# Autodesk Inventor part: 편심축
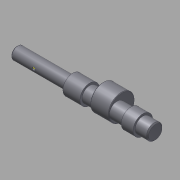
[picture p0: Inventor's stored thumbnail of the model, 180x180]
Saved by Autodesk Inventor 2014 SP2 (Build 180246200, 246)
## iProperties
Company: 한국ATC센터
Created: 2015-12
Part Number: 편심축
Document SubType Name: Modeling
Designer: mdu
Density: 7.86 g/cm^3
Mass: 225.292 g
Surface Area: 81.2402 cm^2
Volume: 28.6631 cm^3
Material: 강철, 연강
Appearance: 강철
Author: mdu
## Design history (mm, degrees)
sketch "스케치1"
  geometry: L1 (-86, 0)-(86, 0); L2 (-86, 0)-(-86, 6); L3 (-86, 6)-(-32, 6); L4 (-32, 6)-(-32, 9.5); L5 (-32, 9.5)-(-15.5, 9.5); L6 (-15.5, 9.5)-(-15.5, 7.5); L7 (-15.5, 7.5)-(48, 7.5); L8 (86, 6)-(86, 0); L9 (36, 7.5)-(36, 9.5); L10 (36, 9.5)-(24.5, 9.5); L11 (24.5, 9.5)-(24.5, 7.5); L12 (48, 7.5)-(48, 6); L13 (48, 6)-(86, 6); 2 further points
  constraints: 26 end point, 6 parallel, 6 perpendicular, 2 point on line, 1 coincident, 1 horizontal, 1 midpoint
  dimensions: "d1" = 12 diameter of L3 L1; "d2" = 15 diameter of L7 L1; "d4" = 16.5 distance of L4.end L5.end; "d5" = 19 diameter of L5 L1; "d24" = 11.5 distance of L9.end L10.end; "d25" = 19 diameter of L10 L1; "d27" = 40 distance between parallel lines of L11 L6; "d28" = 54 distance of L2.end L3.end; "d29" = 50 distance between parallel lines of L8 L9; "d41" = 38 distance between parallel lines of L8 L12; "d42" = 12 diameter of L13 L1
revolve "회전1" stored, may be unused: angle "d6" = 90 deg
node "작업 평면1"
sketch "스케치2"
  geometry: C1 r 7.5 at (0, 0) reference; C2 r 12.5 at (0, 4.5); 1 further point
  constraints: 1 centre point, 1 vertical alignment
  dimensions: "d8" = 4.5 distance of point (0, 0) C2.centre; "d9" = 25 diameter of C2
extrude "돌출1" join sketch "스케치2" distance "d10" = 18; taper "d11" = 0 deg
chamfer "모따기1" distance "d12" = 1; stored, may be unused: second distance "d13" = 2, angle "d14" = 45 deg
chamfer "모따기2" distance "d15" = 0.5; stored, may be unused: second distance "d16" = 2, angle "d17" = 45 deg
node "작업 평면2"
sketch "스케치3"
  geometry: L1 (4, -2)-(18, -2); L2 (18, 2)-(4, 2); L3 (27, 5)-(27, -5) reference; A1 r 2 centre (18, 0) between (18, -2) and (18, 2); A2 r 2 centre (4, 0) between (4, 2) and (4, -2); 2 further points
  constraints: 4 end point, 4 point on circle, 4 tangent, 2 centre point, 1 horizontal, 1 horizontal alignment, 1 midpoint, 1 parallel
  dimensions: "d18" = 7 distance edge to line of A1 L3; "d19" = 4 distance between parallel lines of L2 L1; "d20" = 18 dimension on A1 A2
extrude "돌출2" cut sketch "스케치3" distance "d21" = 2.5; taper "d22" = 0 deg
revolve "회전2" stored, may be unused: angle "d26" = 90 deg
node "작업 평면3"
sketch "스케치4"
  geometry: L1 (44, 5)-(44, -5) reference; 2 further points
  constraints: 1 horizontal alignment
  dimensions: "d30" = 12 distance from line of point (32, 0) L1
hole "구멍1" sketch "스케치4" at (32, 0) diameter "d31" = 6; stored, may be unused: countersink angle "d35" = 90 deg, drill point angle "d37" = 118 deg; dims "d32" = 6, "d33" = 14, "d34" = 3, "d36" = 8
node "작업 평면4"
sketch "스케치5"
  geometry: C1 r 3 at (32, 0) reference; C2 r 8 at (32, 0); 2 further points
  constraints: 1 centre point, 1 coincident, 1 other
  dimensions: "d38" = 16 diameter of C2
extrude "돌출3" cut sketch "스케치5" distance "d39" = 3; taper "d40" = 0 deg
sketch "스케치6"
  geometry: L1 (-85, -6)-(-32, -6) reference; L2 (-86, -5)-(-86, 5) reference; L3 (-85, 6)-(-32, 6) reference; L4 (-64, 6)-(-64, -6); L5 (-64, -6)-(-62.5, -6); L6 (-64, -4.5)-(-62.5, -6); L7 (-64, -6)-(-64, -4.5); 2 further points
  constraints: 8 end point, 4 point on line, 2 perpendicular, 1 coincident
  dimensions: "d43" = 22 distance between parallel lines of L4 L2; "d44" = 45 deg angle of L6 L7; "d45" = 3 diameter of L5.end L4
revolve "회전3" stored, may be unused: angle "d46" = 90 deg
node "작업점1"
chamfer "모따기3" distance "d47" = 0.5; stored, may be unused: second distance "d48" = 2, angle "d49" = 45 deg
sketch "스케치7"
  geometry: C1 r 7.5 at (0, 0) reference; 1 further point
extrude "돌출4" cut sketch "스케치7" stored distance "d50" = 10; taper "d51" = 0 deg
chamfer "모따기4" distance "d52" = 1; stored, may be unused: second distance "d53" = 2, angle "d54" = 45 deg
node "작업 평면5"
node "솔리드1"
node "투영된 루프1"
other parameters: "d7" = 8.5
